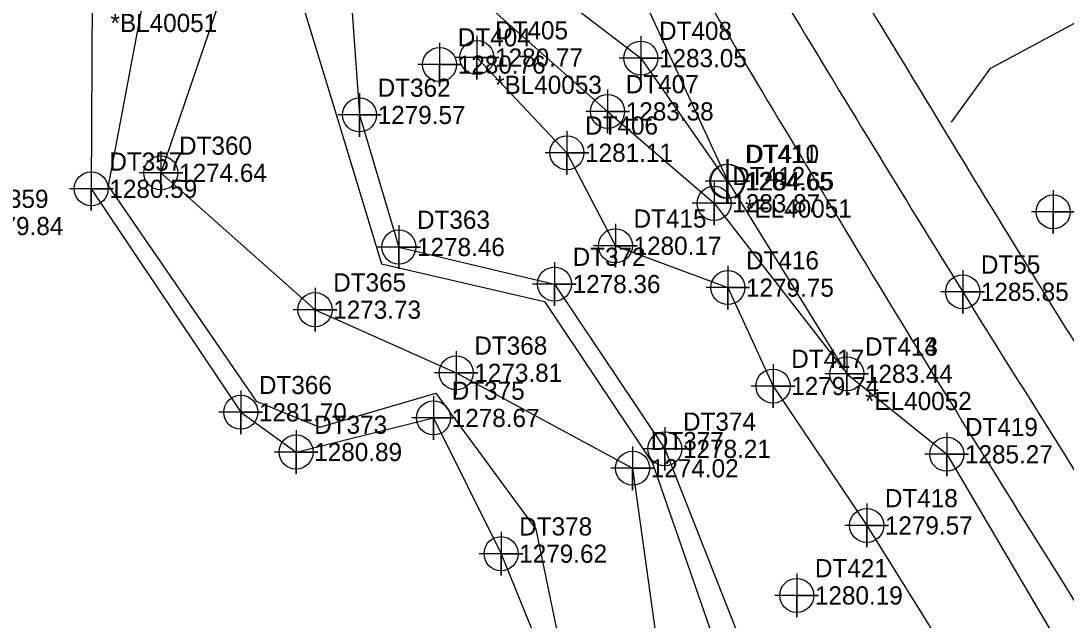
# Model space of a CAD drawing. Extents: x 1394009 to 1394411, y 957864 to 958364.
# Drawn here: x 1394139.9 to 1394283.7, y 957951.9 to 958034.4 of the extents above; entities that cross this region are included whole.
import ezdxf

# ---------------------------------------------------------------- set-up
doc = ezdxf.new("R2010")
doc.units = 0
for name, color, linetype in [('Exist DTM Breakline', 7, 'Continuous'), ('Exist DTM Breakline Cogo Comment', 7, 'Continuous'), ('Exist DTM Breakline Cogo Elevation', 7, 'Continuous'), ('Exist DTM Breakline Cogo Number', 7, 'Continuous'), ('Exist DTM Breakline Cogo Point CELL', 7, 'Continuous'), ('Exist DTM Breakline Underwater', 7, 'Continuous'), ('Exist DTM Breakline Underwater Cogo Elevation', 7, 'Continuous'), ('Exist DTM Breakline Underwater Cogo Number', 7, 'Continuous'), ('Exist DTM Breakline Underwater Cogo Point CELL', 7, 'Continuous'), ('Exist DTM Crownline', 7, 'Continuous'), ('Exist DTM Regular Point Cogo Elevation', 7, 'Continuous'), ('Exist Hydro Stream or Body of Water', 7, 'Continuous'), ('Exist Roads EOP', 7, 'Continuous'), ('Exist Roads Soil', 7, 'Continuous'), ('Exist Structure Minor Culvert Topo', 7, 'Continuous'), ('Exist Structure Minor Culvert Topo Terminator', 7, 'Continuous'), ('Exist Structure Minor Footbridge Terminator', 7, 'Continuous'), ('PH Exist DTM NCFMP LIDAR Elevation Point', 7, 'Continuous'), ('Raster_Level_0', 7, 'Continuous')]:
    doc.layers.add(name, color=color, linetype=linetype)

msp = doc.modelspace()

# ---------------------------------------------------------------- linework, layer by layer
at = {"layer": 'Exist DTM Breakline'}
for points in [[(1394234.7161, 958087.1493), (1394208.4745, 958071.86), (1394207.051, 958069.7897), (1394210.8783, 958071.9618), (1394213.0858, 958066.3393), (1394211.818, 958067.823), (1394208.5647, 958061.9703), (1394223.9737, 958040.8216), (1394237.157, 958012.3346), (1394253.5006, 957985.8224), (1394267.2603, 957974.749), (1394288.6525, 957938.4432), (1394308.2436, 957898.2998)], [(1394207.2831, 958069.7981), (1394199.3051, 958059.0705), (1394207.0076, 958043.1259), (1394225.1737, 958029.2554), (1394237.0033, 958012.304)], [(1394205.7466, 958068.8917), (1394190.5711, 958057.2067), (1394189.0222, 958053.5957), (1394184.8806, 958043.8407), (1394186.4655, 958021.4355), (1394191.8774, 958003.2638), (1394213.2872, 957998.1706), (1394228.4733, 957975.4923), (1394239.8888, 957946.4968), (1394241.0497, 957903.4511)], [(1394191.8454, 958052.8419), (1394201.7992, 958038.6118), (1394220.6022, 958021.9205), (1394235.2523, 958009.2773), (1394253.0852, 957986.3641)], [(1394149.71, 958037.8453), (1394149.558, 958011.2722), (1394170.1298, 957980.5225), (1394177.7403, 957975.0583), (1394196.6522, 957979.7455), (1394205.9408, 957961.0676), (1394214.1868, 957940.8417), (1394207.8738, 957917.8382)], [(1394202.6193, 958029.3354), (1394215.0019, 958016.2345), (1394221.6713, 958003.4334), (1394237.1401, 957997.6779), (1394243.3584, 957984.1351), (1394256.2425, 957964.9576), (1394277.0443, 957931.6004), (1394291.0752, 957911.067), (1394259.429, 957904.1903), (1394243.1444, 957902.5266)]]:
    msp.add_lwpolyline(points, dxfattribs=at)
at = {"layer": 'Exist DTM Breakline Cogo Point CELL'}
for points in [[(1394202.6193, 958032.3354), (1394202.6193, 958026.3354), (1394202.6193, 958029.3354), (1394205.6193, 958029.3354), (1394199.6193, 958029.3354)], [(1394225.1737, 958032.2554), (1394225.1737, 958026.2554), (1394225.1737, 958029.2554), (1394228.1737, 958029.2554), (1394222.1737, 958029.2554)], [(1394186.4655, 958024.4355), (1394186.4655, 958018.4355), (1394186.4655, 958021.4355), (1394189.4655, 958021.4355), (1394183.4655, 958021.4355)], [(1394220.6022, 958024.9205), (1394220.6022, 958018.9205), (1394220.6022, 958021.9205), (1394223.6022, 958021.9205), (1394217.6022, 958021.9205)], [(1394215.0019, 958019.2345), (1394215.0019, 958013.2345), (1394215.0019, 958016.2345), (1394218.0019, 958016.2345), (1394212.0019, 958016.2345)], [(1394149.558, 958014.2722), (1394149.558, 958008.2722), (1394149.558, 958011.2722), (1394152.558, 958011.2722), (1394146.558, 958011.2722)], [(1394237.0033, 958015.304), (1394237.0033, 958009.304), (1394237.0033, 958012.304), (1394240.0033, 958012.304), (1394234.0033, 958012.304)], [(1394237.157, 958015.3346), (1394237.157, 958009.3346), (1394237.157, 958012.3346), (1394240.157, 958012.3346), (1394234.157, 958012.3346)], [(1394235.2523, 958012.2773), (1394235.2523, 958006.2773), (1394235.2523, 958009.2773), (1394238.2523, 958009.2773), (1394232.2523, 958009.2773)], [(1394191.8774, 958006.2638), (1394191.8774, 958000.2638), (1394191.8774, 958003.2638), (1394194.8774, 958003.2638), (1394188.8774, 958003.2638)], [(1394221.6713, 958006.4334), (1394221.6713, 958000.4334), (1394221.6713, 958003.4334), (1394224.6713, 958003.4334), (1394218.6713, 958003.4334)], [(1394213.2872, 958001.1706), (1394213.2872, 957995.1706), (1394213.2872, 957998.1706), (1394216.2872, 957998.1706), (1394210.2872, 957998.1706)], [(1394237.1401, 958000.6779), (1394237.1401, 957994.6779), (1394237.1401, 957997.6779), (1394240.1401, 957997.6779), (1394234.1401, 957997.6779)], [(1394253.5006, 957988.8224), (1394253.5006, 957982.8224), (1394253.5006, 957985.8224), (1394256.5006, 957985.8224), (1394250.5006, 957985.8224)], [(1394253.5084, 957988.8203), (1394253.5084, 957982.8203), (1394253.5084, 957985.8203), (1394256.5084, 957985.8203), (1394250.5084, 957985.8203)], [(1394243.3584, 957987.1351), (1394243.3584, 957981.1351), (1394243.3584, 957984.1351), (1394246.3584, 957984.1351), (1394240.3584, 957984.1351)], [(1394170.1298, 957983.5225), (1394170.1298, 957977.5225), (1394170.1298, 957980.5225), (1394173.1298, 957980.5225), (1394167.1298, 957980.5225)], [(1394196.6522, 957982.7455), (1394196.6522, 957976.7455), (1394196.6522, 957979.7455), (1394199.6522, 957979.7455), (1394193.6522, 957979.7455)], [(1394228.4733, 957978.4923), (1394228.4733, 957972.4923), (1394228.4733, 957975.4923), (1394231.4733, 957975.4923), (1394225.4733, 957975.4923)], [(1394177.7403, 957978.0583), (1394177.7403, 957972.0583), (1394177.7403, 957975.0583), (1394180.7403, 957975.0583), (1394174.7403, 957975.0583)], [(1394267.2603, 957977.749), (1394267.2603, 957971.749), (1394267.2603, 957974.749), (1394270.2603, 957974.749), (1394264.2603, 957974.749)], [(1394256.2425, 957967.9576), (1394256.2425, 957961.9576), (1394256.2425, 957964.9576), (1394259.2425, 957964.9576), (1394253.2425, 957964.9576)], [(1394205.9408, 957964.0676), (1394205.9408, 957958.0676), (1394205.9408, 957961.0676), (1394208.9408, 957961.0676), (1394202.9408, 957961.0676)]]:
    msp.add_lwpolyline(points, dxfattribs=at)
for centre in [(1394202.6193, 958029.3354), (1394225.1737, 958029.2554), (1394186.4655, 958021.4355), (1394220.6022, 958021.9205), (1394215.0019, 958016.2345), (1394237.0033, 958012.304), (1394237.157, 958012.3346), (1394149.558, 958011.2722), (1394235.2523, 958009.2773), (1394221.6713, 958003.4334), (1394191.8774, 958003.2638), (1394213.2872, 957998.1706), (1394237.1401, 957997.6779), (1394253.5006, 957985.8224), (1394253.5084, 957985.8203), (1394243.3584, 957984.1351), (1394170.1298, 957980.5225), (1394196.6522, 957979.7455), (1394177.7403, 957975.0583), (1394228.4733, 957975.4923), (1394267.2603, 957974.749), (1394256.2425, 957964.9576), (1394205.9408, 957961.0676)]:
    msp.add_circle(centre, 2.344, dxfattribs=at)
at = {"layer": 'Exist DTM Breakline Underwater'}
msp.add_lwpolyline([(1394192.3583, 958090.5901), (1394178.3868, 958072.1738), (1394169.2021, 958057.4892), (1394167.6851, 958038.5052), (1394159.1429, 958013.4636), (1394180.3464, 957994.6406), (1394199.7643, 957985.953), (1394224.0434, 957972.821), (1394228.1265, 957943.556), (1394220.9394, 957914.628)], dxfattribs=at)
at = {"layer": 'Exist DTM Breakline Underwater Cogo Point CELL'}
for points in [[(1394159.1429, 958016.4636), (1394159.1429, 958010.4636), (1394159.1429, 958013.4636), (1394162.1429, 958013.4636), (1394156.1429, 958013.4636)], [(1394180.3464, 957997.6406), (1394180.3464, 957991.6406), (1394180.3464, 957994.6406), (1394183.3464, 957994.6406), (1394177.3464, 957994.6406)], [(1394199.7643, 957988.953), (1394199.7643, 957982.953), (1394199.7643, 957985.953), (1394202.7643, 957985.953), (1394196.7643, 957985.953)], [(1394224.0434, 957975.821), (1394224.0434, 957969.821), (1394224.0434, 957972.821), (1394227.0434, 957972.821), (1394221.0434, 957972.821)]]:
    msp.add_lwpolyline(points, dxfattribs=at)
for centre in [(1394159.1429, 958013.4636), (1394180.3464, 957994.6406), (1394199.7643, 957985.953), (1394224.0434, 957972.821)]:
    msp.add_circle(centre, 2.344, dxfattribs=at)
at = {"layer": 'Exist DTM Crownline'}
msp.add_spline([(1394223.6604, 958072.3799), (1394244.8218, 958037.3795), (1394269.4506, 957997.0996), (1394294.4399, 957957.1952), (1394318.0033, 957919.003)], degree=3, dxfattribs=at)
at = {"layer": 'Exist Hydro Stream or Body of Water'}
for points in [[(1394190.7058, 958095.3239), (1394177.2279, 958076.1665), (1394160.3309, 958063.4331), (1394156.4808, 958036.0172), (1394151.8807, 958011.6814), (1394172.2345, 957982.059), (1394181.0188, 957978.4843), (1394196.9657, 957983.1686), (1394210.7106, 957964.4319), (1394215.4703, 957941.598), (1394209.5541, 957917.1532)], [(1394203.9517, 958072.4517), (1394187.582, 958060.0115), (1394178.1893, 958051.3287), (1394177.8231, 958039.3974), (1394183.6296, 958020.3053), (1394189.4903, 958000.9486), (1394211.9273, 957995.783), (1394226.7784, 957973.5412), (1394236.5763, 957945.2073), (1394231.9355, 957908.562)]]:
    msp.add_lwpolyline(points, dxfattribs=at)
at = {"layer": 'Exist Roads EOP'}
for points in [[(1394231.4675, 958077.1435), (1394252.9816, 958042.2643), (1394277.1668, 958002.5538), (1394302.3527, 957962.1709), (1394325.7525, 957924.4929)], [(1394215.8384, 958067.9044), (1394237.3577, 958032.1628), (1394261.7049, 957991.7458), (1394286.4849, 957951.9331), (1394310.1777, 957914.0367)]]:
    msp.add_spline(points, degree=3, dxfattribs=at)
at = {"layer": 'Exist Roads Soil'}
msp.add_lwpolyline([(1394306.4285, 957956.718), (1394315.1027, 957959.6918), (1394333.9061, 957973.0572), (1394347.2179, 957982.7667), (1394355.735, 958004.7936), (1394347.3044, 958036.1133), (1394332.8906, 958044.0577), (1394314.1398, 958043.6186), (1394287.8803, 958035.6785), (1394273.189, 958027.7647), (1394267.8535, 958020.4329)], dxfattribs=at)
at = {"layer": 'Exist Structure Minor Culvert Topo Terminator'}
msp.add_lwpolyline([(1394269.4506, 958000.0996), (1394269.4506, 957994.0996), (1394269.4506, 957997.0996), (1394272.4506, 957997.0996), (1394266.4506, 957997.0996)], dxfattribs=at)
msp.add_circle((1394269.4506, 957997.0996), 2.344, dxfattribs=at)
at = {"layer": 'PH Exist DTM NCFMP LIDAR Elevation Point'}
for points in [[(1394197.4874, 958031.3651), (1394197.4874, 958025.3651), (1394197.4874, 958028.3651), (1394200.4874, 958028.3651), (1394194.4874, 958028.3651)], [(1394281.9056, 958011.1035), (1394281.9056, 958005.1035), (1394281.9056, 958008.1035), (1394284.9056, 958008.1035), (1394278.9056, 958008.1035)], [(1394246.6179, 957958.3263), (1394246.6179, 957952.3263), (1394246.6179, 957955.3263), (1394249.6179, 957955.3263), (1394243.6179, 957955.3263)]]:
    msp.add_lwpolyline(points, dxfattribs=at)
for centre in [(1394197.4874, 958028.3651), (1394281.9056, 958008.1035), (1394246.6179, 957955.3263)]:
    msp.add_circle(centre, 2.344, dxfattribs=at)

# ---------------------------------------------------------------- texts
at = {"layer": 'Exist DTM Breakline Cogo Comment'}
for s, p in [('*BL40051', (1394152.21, 958032.8453)), ('*BL40053', (1394205.1193, 958024.3354)), ('*EL40051', (1394239.5033, 958007.304)), ('*EL40052', (1394256.0084, 957980.8203))]:
    msp.add_text(s, height=2.5, dxfattribs=at).set_placement(p)
at = {"layer": 'Exist DTM Breakline Cogo Elevation'}
for s, p in [('1280.77', (1394205.1193, 958028.0854)), ('1283.05', (1394227.6737, 958028.0054)), ('1283.38', (1394223.1022, 958020.6705)), ('1279.57', (1394188.9655, 958020.1855)), ('1281.11', (1394217.5019, 958014.9845)), ('1284.65', (1394239.5033, 958011.054)), ('1284.65', (1394239.657, 958011.0846)), ('1280.59', (1394152.058, 958010.0222)), ('1283.87', (1394237.7523, 958008.0273)), ('1278.46', (1394194.3774, 958002.0138)), ('1280.17', (1394224.1713, 958002.1834)), ('1278.36', (1394215.7872, 957996.9206)), ('1279.75', (1394239.6401, 957996.4279)), ('1283.44', (1394256.0006, 957984.5724)), ('1283.44', (1394256.0084, 957984.5703)), ('1279.74', (1394245.8584, 957982.8851)), ('1281.70', (1394172.6298, 957979.2725)), ('1278.67', (1394199.1522, 957978.4955)), ('1280.89', (1394180.2403, 957973.8083)), ('1278.21', (1394230.9733, 957974.2423)), ('1285.27', (1394269.7603, 957973.499)), ('1279.57', (1394258.7425, 957963.7076)), ('1279.62', (1394208.4408, 957959.8176))]:
    msp.add_text(s, height=2.5, dxfattribs=at).set_placement(p)
at = {"layer": 'Exist DTM Breakline Cogo Number'}
for s, p in [('DT405', (1394205.1193, 958031.8354)), ('DT408', (1394227.6737, 958031.7554)), ('DT362', (1394188.9655, 958023.9355)), ('DT407', (1394223.1022, 958024.4205)), ('DT406', (1394217.5019, 958018.7345)), ('DT411', (1394239.5033, 958014.804)), ('DT410', (1394239.657, 958014.8346)), ('DT357', (1394152.058, 958013.7722)), ('DT412', (1394237.7523, 958011.7773)), ('DT363', (1394194.3774, 958005.7638)), ('DT415', (1394224.1713, 958005.9334)), ('DT372', (1394215.7872, 958000.6706)), ('DT416', (1394239.6401, 958000.1779)), ('DT414', (1394256.0006, 957988.3224)), ('DT413', (1394256.0084, 957988.3203)), ('DT417', (1394245.8584, 957986.6351)), ('DT366', (1394172.6298, 957983.0225)), ('DT375', (1394199.1522, 957982.2455)), ('DT373', (1394180.2403, 957977.5583)), ('DT374', (1394230.9733, 957977.9923)), ('DT419', (1394269.7603, 957977.249)), ('DT418', (1394258.7425, 957967.4576)), ('DT378', (1394208.4408, 957963.5676))]:
    msp.add_text(s, height=2.5, dxfattribs=at).set_placement(p)
at = {"layer": 'Exist DTM Breakline Underwater Cogo Elevation'}
for s, p in [('1274.64', (1394161.6429, 958012.2136)), ('1273.73', (1394182.8464, 957993.3906)), ('1273.81', (1394202.2643, 957984.703)), ('1274.02', (1394226.5434, 957971.571))]:
    msp.add_text(s, height=2.5, dxfattribs=at).set_placement(p)
at = {"layer": 'Exist DTM Breakline Underwater Cogo Number'}
for s, p in [('DT360', (1394161.6429, 958015.9636)), ('DT365', (1394182.8464, 957997.1406)), ('DT368', (1394202.2643, 957988.453)), ('DT377', (1394226.5434, 957975.321))]:
    msp.add_text(s, height=2.5, dxfattribs=at).set_placement(p)
at = {"layer": 'Exist DTM Regular Point Cogo Elevation'}
for s, p in [('1280.76', (1394199.9874, 958027.1151)), ('1279.84', (1394133.6475, 958004.8958)), ('1280.19', (1394249.1179, 957954.0763))]:
    msp.add_text(s, height=2.5, dxfattribs=at).set_placement(p)
at = {"layer": 'Exist Structure Minor Culvert Topo'}
msp.add_text('DT55', height=2.5, dxfattribs=at).set_placement((1394271.9506, 957999.5996))
at = {"layer": 'Exist Structure Minor Footbridge Terminator'}
msp.add_text('1285.85', height=2.5, dxfattribs=at).set_placement((1394271.9506, 957995.8496))
at = {"layer": 'Raster_Level_0'}
for s, p in [('DT404', (1394199.9874, 958030.8651)), ('DT359', (1394133.6475, 958008.6458)), ('DT421', (1394249.1179, 957957.8263))]:
    msp.add_text(s, height=2.5, dxfattribs=at).set_placement(p)

doc.saveas('drawing.dxf')
